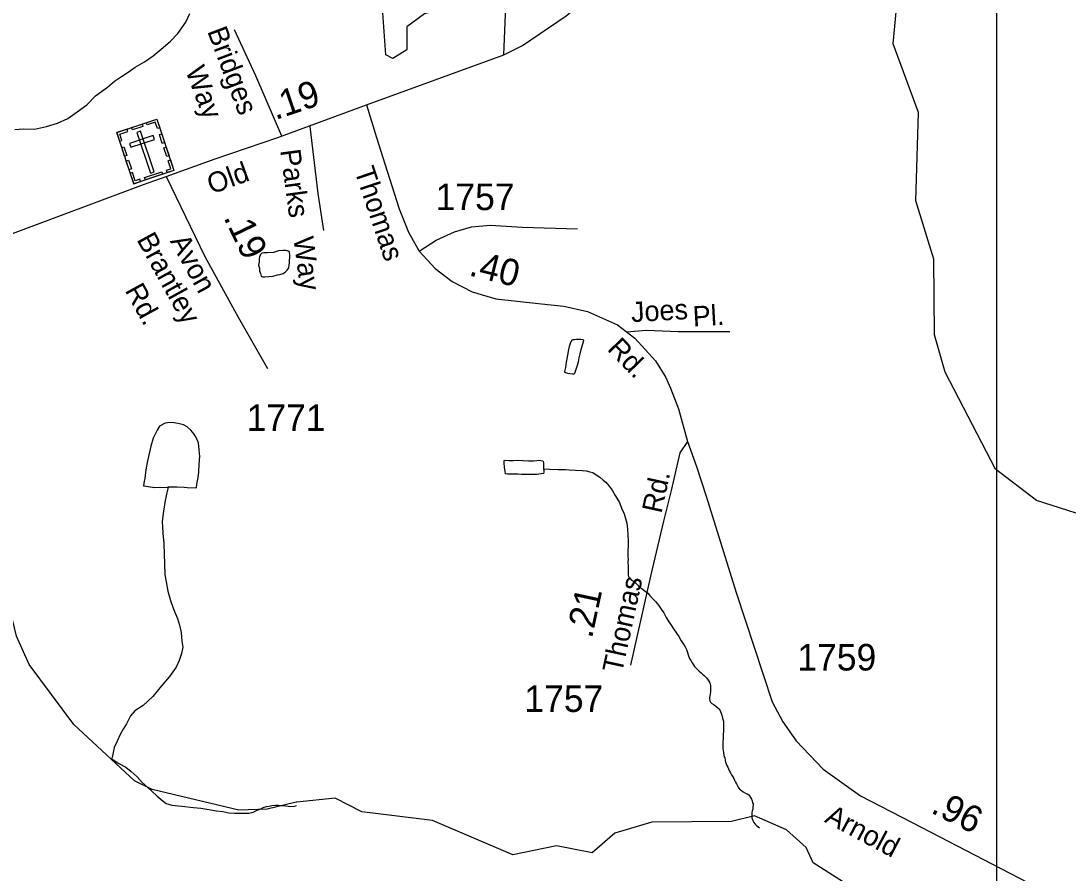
# Model space of a CAD drawing. Extents: x 2126262 to 2293712, y 749403 to 919119.
# Drawn here: x 2220963 to 2225896, y 775853 to 779867 of the extents above; entities that cross this region are included whole.
import ezdxf

# ---------------------------------------------------------------- set-up
doc = ezdxf.new("R2010")
doc.units = 0
for name, color, linetype in [('Exist Cultural Cemetery CELL', 7, 'Continuous'), ('Exist Hydrographic Creek Single Shore', 7, 'Continuous'), ('Exist Hydrographic Misc Water Feature', 7, 'Continuous'), ('Exist Hydrographic Pond Over 1500 Sq Ft', 7, 'Continuous'), ('Exist Road Non-System Type 51', 7, 'Continuous'), ('Exist Road Non-System Type 51 Label', 7, 'Continuous'), ('Exist Road Secondary Mileage Hundredths English Label', 7, 'Continuous'), ('Exist Road Secondary Type 41 Attributed', 7, 'Continuous'), ('Exist Road Secondary Type 51 Attributed', 7, 'Continuous'), ('Exist Road Secondary Type 51 Label', 7, 'Continuous'), ('Exist Road Secondary Type 51 Number Label', 7, 'Continuous'), ('Map Preparation Inset Cut Line', 7, 'Continuous')]:
    doc.layers.add(name, color=color, linetype=linetype)

msp = doc.modelspace()

# ---------------------------------------------------------------- linework, layer by layer
at = {"layer": 'Exist Cultural Cemetery CELL'}
for points in [[(2221414.4, 779341.1), (2221603.1, 779404.3), (2221684, 779162.9), (2221495.2, 779099.7)], [(2221484.6, 779364.6), (2221533.7, 779381.1), (2221537.4, 779370.3), (2221488.2, 779353.8)], [(2221617, 779363.2), (2221606.2, 779359.6), (2221596, 779390.2), (2221557.5, 779377.3), (2221554, 779387.8), (2221603.2, 779404.3)], [(2221428.1, 779300), (2221438.9, 779303.7), (2221428.6, 779334.2), (2221467.1, 779347), (2221463.6, 779357.6), (2221414.4, 779341.1)], [(2221474.7, 779289.5), (2221480.6, 779271.8), (2221592.2, 779309.2), (2221586.3, 779326.9)], [(2221527, 779348), (2221509.3, 779342), (2221573.7, 779149.7), (2221591.4, 779155.7)], [(2221629.3, 779290.3), (2221615.6, 779331.4), (2221626.4, 779335), (2221640.1, 779293.9)], [(2221451.6, 779229.7), (2221437.9, 779270.8), (2221448.7, 779274.4), (2221462.4, 779233.3)], [(2221650.2, 779227.8), (2221636.5, 779268.9), (2221647.3, 779272.5), (2221661, 779231.4)], [(2221652.6, 779152.4), (2221648.9, 779163.3), (2221669.8, 779170.2), (2221656.9, 779208.6), (2221667.5, 779212.1), (2221684, 779162.9)], [(2221473, 779166), (2221459.2, 779207.1), (2221470, 779210.7), (2221483.7, 779169.6)], [(2221526.5, 779110.2), (2221522.9, 779121.1), (2221502, 779114.1), (2221489.2, 779152.4), (2221478.6, 779148.9), (2221495.1, 779099.7)], [(2221546, 779128.8), (2221626.5, 779155.7), (2221630.1, 779144.9), (2221549.6, 779118)]]:
    msp.add_lwpolyline(points, close=True, dxfattribs=at)
at = {"layer": 'Exist Hydrographic Creek Single Shore'}
for points in [[(2227377, 776045), (2227258, 776296.7), (2227265, 776486.8), (2227240, 776503.7), (2227222, 776635.3), (2227171.9, 776685.6), (2226997, 776708.8), (2226745, 776950.2), (2226684.9, 777115.5), (2226592, 777255.1), (2226334.1, 777296.5), (2226082.1, 777501.8), (2225748, 777607.1), (2225555.1, 777755.3), (2225318, 778212.9), (2225267, 778387.8), (2225263.9, 778745.4), (2225179, 779019.4), (2225191.9, 779435.7), (2225072, 779759.7), (2225103, 780093.6)], [(2222260.2, 776186.5), (2222122.9, 776153.1), (2221989.8, 776149.3), (2221580.9, 776246.2), (2221497.9, 776287.4), (2221212.9, 776552.3), (2221001.9, 776835.5), (2220943, 776967.9), (2220780, 777633.8), (2220687.9, 777806.3), (2220326, 778263.1)], [(2224418.9, 776122.3), (2224311, 776094.9), (2223936, 776092.8), (2223761.9, 776040.7), (2223654, 775947.8), (2223486.9, 775980.7), (2223280, 775939), (2222902.9, 776100.9), (2222569.9, 776140.6), (2222444, 776205.6), (2222262.7, 776187.1)], [(2225985.9, 774387), (2225979.9, 774406.6), (2225972.7, 774423.7), (2225976.8, 774466.1), (2225985.3, 774509.9), (2225969, 774563.2), (2225976.4, 774612.2), (2225958.7, 774657.9), (2225952.1, 774702.5), (2225968.5, 774735.1), (2225943.4, 774771), (2225910.8, 774785.1), (2225890.1, 774788.4), (2225862, 774869), (2225817.9, 775207.8), (2225515.9, 775446.9), (2224929.8, 775750.9), (2224695.9, 775900.1), (2224661.8, 775972.9), (2224570, 776056.9), (2224418.9, 776122.3)]]:
    msp.add_lwpolyline(points, dxfattribs=at)
at = {"layer": 'Exist Hydrographic Misc Water Feature'}
for points in [[(2220935.1, 779356.3), (2220975.5, 779358.7), (2221027, 779357), (2221083, 779369.6), (2221135, 779385.7), (2221184.7, 779408.2), (2221228.3, 779438.5), (2221274.5, 779472.6), (2221314.2, 779514.9), (2221371.5, 779555.3), (2221403.4, 779583.7), (2221437.7, 779605.8), (2221469.1, 779626.2), (2221501.1, 779650.1), (2221544.7, 779674.4), (2221586.8, 779702.9), (2221633.9, 779741.2), (2221668.4, 779771.3), (2221702, 779807.6), (2221739.5, 779861.6), (2221759.4, 779902)], [(2222183.3, 778673.3), (2222199.3, 778677.4), (2222209.7, 778685.5), (2222216.9, 778693.4), (2222224.9, 778703.5), (2222227.3, 778717.8), (2222229, 778725.6), (2222230.6, 778765.6), (2222228.8, 778775.6), (2222226.9, 778781.5), (2222212.6, 778785.3), (2222196.8, 778785.2), (2222176.7, 778783.5), (2222152.5, 778776.9), (2222124.6, 778775), (2222106.8, 778774.9), (2222098.8, 778772.9), (2222093, 778768.5), (2222086.7, 778756.8), (2222085.2, 778744.5), (2222085.2, 778732.7), (2222083, 778716.5), (2222087.1, 778702.5), (2222087.3, 778688.6), (2222091.2, 778676.6), (2222095.7, 778664.6), (2222101.9, 778660.8), (2222111.7, 778661), (2222131.4, 778662.9), (2222151.5, 778665.1), (2222171.6, 778671), (2222183.3, 778673.3)], [(2223537.4, 778291.9), (2223531.7, 778260), (2223528, 778234.2), (2223523.9, 778215.7), (2223523.9, 778212.1), (2223538.4, 778207.9), (2223549.9, 778206.1), (2223562, 778204.3), (2223570, 778204.3), (2223572.1, 778208.4), (2223583.8, 778240.4), (2223589.7, 778260.6), (2223593.4, 778280.7), (2223597.3, 778298.8), (2223603, 778318.6), (2223609, 778340.8), (2223613.1, 778354.8), (2223614.7, 778362.6), (2223610.8, 778364.5), (2223598.7, 778366.7), (2223580.5, 778366.6), (2223570.8, 778364.4), (2223562.9, 778364.4), (2223556.9, 778362.1), (2223551.2, 778347.9), (2223546.7, 778334), (2223543, 778319.9), (2223537.4, 778291.9)], [(2221658.9, 777672.2), (2221698.9, 777672.2), (2221732.6, 777670.8), (2221746.7, 777668.6), (2221790.6, 777666.9), (2221792.4, 777684.9), (2221798.2, 777716.9), (2221802.1, 777743.1), (2221803.7, 777778.9), (2221805.6, 777815.1), (2221803.7, 777847.1), (2221799.2, 777879), (2221788.9, 777904.9), (2221778.9, 777921), (2221762.9, 777938.8), (2221746.7, 777954.6), (2221728.5, 777964.3), (2221704.3, 777970.4), (2221672.5, 777976), (2221654.2, 777973.9), (2221642.5, 777972), (2221616.7, 777957.7), (2221604.4, 777939.6), (2221587, 777901.3), (2221575.1, 777863.3), (2221557.9, 777787.2), (2221554, 777761.5), (2221550.3, 777739.3), (2221546.6, 777711.4), (2221544.5, 777699.2), (2221542.5, 777687.3), (2221540.8, 777677), (2221562.6, 777673.3), (2221592.7, 777669.6), (2221652.6, 777669.9), (2221658.9, 777672.2)], [(2223425.5, 777757.2), (2223425.9, 777749.4), (2223425.9, 777741.3), (2223425.7, 777735.2), (2223391.8, 777731), (2223371.9, 777730.8), (2223351.9, 777731), (2223322.1, 777730.6), (2223305.9, 777732.3), (2223291.8, 777732.3), (2223278.2, 777731.9), (2223266.3, 777732.1), (2223256.1, 777732.1), (2223246.3, 777733.9), (2223244, 777746), (2223241.7, 777763.8), (2223239.5, 777785.7), (2223239.5, 777793.8), (2223241.5, 777797.9), (2223263.3, 777795.9), (2223281.5, 777795.9), (2223301.4, 777798.2), (2223353.7, 777794.8), (2223377.5, 777794.8), (2223393.5, 777796.9), (2223405.4, 777797.1), (2223421.2, 777795.1), (2223423.6, 777791.1), (2223425.5, 777785.2), (2223425.7, 777773.4), (2223425.5, 777757.2)], [(2223425.5, 777757.2), (2223455.4, 777755.5), (2223493.7, 777753.7), (2223509.5, 777754.2), (2223528, 777754.3), (2223545.4, 777752.5), (2223575.8, 777750.7), (2223607.8, 777748.7), (2223625.6, 777746.8), (2223643.8, 777743.3), (2223658, 777739.1), (2223673.8, 777729.4), (2223690.2, 777717.6), (2223706.2, 777703.9), (2223718.5, 777693.9), (2223734.7, 777676), (2223748.2, 777656.1), (2223762.6, 777632), (2223782.9, 777598.2), (2223792.9, 777572.3), (2223805.4, 777544.4), (2223812, 777522.7), (2223817.5, 777500.8), (2223820.2, 777472.8), (2223822.2, 777444.5), (2223824.5, 777416.6), (2223824.7, 777394.7), (2223822.7, 777370.6), (2223822.7, 777344.7), (2223823.3, 777330.8), (2223823.1, 777316.6), (2223823.5, 777298.7), (2223823.7, 777289), (2223823.7, 777274.7), (2223823.7, 777266.6), (2223823.7, 777256.9), (2223825.9, 777248.8), (2223830, 777243), (2223839.7, 777233), (2223849.7, 777227), (2223857.9, 777219.3), (2223870.4, 777207.3), (2223882.3, 777197.3), (2223898.1, 777185.6), (2223916.2, 777171.5), (2223926.6, 777159.8), (2223938.7, 777145.8), (2223952.7, 777132), (2223967, 777114), (2223978.9, 777095.9), (2223991.2, 777078.2), (2224003.3, 777056.6), (2224015.2, 777036.5), (2224023.6, 777024.7), (2224037.8, 777002.7), (2224051.9, 776982.7), (2224061.9, 776967), (2224074.3, 776946.9), (2224084.1, 776931.2), (2224092.7, 776918.9), (2224098.4, 776905.1), (2224102.8, 776891), (2224106.6, 776881.1), (2224113, 776863.1), (2224119.2, 776853.3), (2224125.1, 776843.5), (2224131.1, 776833.6), (2224137, 776825.4), (2224143.1, 776819.6), (2224151.1, 776811.5), (2224157.1, 776805.8), (2224167.3, 776795.7), (2224173.5, 776789.9), (2224181.5, 776783.8), (2224187.2, 776778.1), (2224193.6, 776771.8), (2224201.6, 776762.1), (2224207.7, 776752.3), (2224209.8, 776744.3), (2224211.8, 776734.2), (2224211.8, 776724.1), (2224212, 776714.3), (2224212.3, 776706.2), (2224210.2, 776696.3), (2224207.9, 776688.1), (2224206.7, 776680.2), (2224206.5, 776674.1), (2224208.4, 776664.1), (2224212.5, 776658.2), (2224218.2, 776652.1), (2224228.9, 776644.5), (2224236.7, 776638.4), (2224246.9, 776630.4), (2224250.4, 776626.6), (2224256.7, 776618.7), (2224260.6, 776608.8), (2224265.2, 776596.8), (2224269.1, 776582.8), (2224273.2, 776568.8), (2224273.4, 776554.5)], [(2221658.9, 777672.2), (2221654.6, 777663.9), (2221646.8, 777630.2), (2221643.2, 777608), (2221635.4, 777558.1), (2221631.7, 777535.9), (2221629.4, 777507.9), (2221630, 777485.9), (2221632.1, 777451.9), (2221636.4, 777406.2), (2221638.8, 777351.9), (2221639.5, 777312.1), (2221641.5, 777258.2), (2221647.7, 777224), (2221655.7, 777180.2), (2221668.4, 777136.5), (2221680.7, 777100.5), (2221686.4, 777084.6), (2221701.2, 777052.5), (2221711, 777020.5), (2221717.4, 776986.7), (2221721.9, 776944.7), (2221725.8, 776916.9), (2221719.8, 776886.9), (2221708.2, 776854.6), (2221694.4, 776822.6), (2221662.6, 776778.3), (2221617.1, 776726), (2221585.3, 776684.1), (2221539.6, 776641.5), (2221500, 776617.5), (2221480.1, 776593.3), (2221460.2, 776555.4), (2221444.9, 776530.9), (2221430.7, 776505), (2221417.2, 776474.6), (2221403.2, 776444.7), (2221393.6, 776396.6), (2221389.5, 776390.8)], [(2224273.4, 776554.5), (2224273.4, 776538.8), (2224273.6, 776522.9), (2224271.9, 776504.9), (2224271.7, 776486.6), (2224269.7, 776468.7), (2224270.1, 776450.8), (2224270.3, 776439), (2224272.3, 776420.8), (2224274.2, 776406.7), (2224278.7, 776394.8), (2224280.9, 776383), (2224283, 776375), (2224285, 776367), (2224288.7, 776359.1), (2224293, 776350.8), (2224296.7, 776343.3), (2224301, 776332.9), (2224305.3, 776325), (2224311.3, 776315.1), (2224317.2, 776305.3), (2224321.5, 776297.4), (2224325.2, 776289.5), (2224329.3, 776281.2), (2224333.6, 776273.3), (2224339.6, 776263.4), (2224343.5, 776253.5), (2224351.9, 776245.3), (2224357.6, 776241.6), (2224366, 776235.5), (2224376.1, 776229.5), (2224383.9, 776225.9), (2224391.7, 776221.8), (2224396, 776215.9), (2224400.1, 776208.1), (2224404.4, 776200.1), (2224408.5, 776192.2), (2224410.1, 776184.2), (2224412.6, 776178.2), (2224412.4, 776172.1), (2224410.7, 776164.3), (2224410.7, 776154.1), (2224408.5, 776145.9), (2224406.8, 776136), (2224406.8, 776125.9), (2224406.6, 776112.1), (2224410.9, 776100.1), (2224415.3, 776090.1), (2224421.2, 776084.4), (2224429.2, 776076.3), (2224443.3, 776066.4)], [(2221389.5, 776390.8), (2221393.4, 776388.5), (2221423.7, 776369), (2221457.8, 776351.3), (2221482.2, 776331.3), (2221510.1, 776305.7), (2221534.3, 776279.7), (2221560.5, 776255.8), (2221580.4, 776238.2), (2221604.6, 776214.3), (2221632.9, 776190.6), (2221647, 776180.7), (2221659.1, 776176.8), (2221674.9, 776172.8), (2221720.9, 776167.1), (2221776.8, 776161.5), (2221810.9, 776157.6), (2221884.7, 776146.4), (2221914.6, 776142.3), (2221943.1, 776136.8), (2221969.2, 776134.9), (2221999.3, 776135.2), (2222021.1, 776135.2), (2222037.1, 776135.2), (2222056.9, 776139.5), (2222076.8, 776149.5), (2222092.8, 776155.6), (2222104.9, 776161.9), (2222120.9, 776166), (2222132.8, 776168.2), (2222144.5, 776170.5), (2222162.8, 776172.6), (2222176.9, 776172.9), (2222191.1, 776171.2), (2222209.1, 776169.7), (2222235.1, 776166.1), (2222253, 776168.3), (2222261, 776170.4)], [(2222262.7, 776187.1), (2222260.2, 776186.5)]]:
    msp.add_lwpolyline(points, dxfattribs=at)
at = {"layer": 'Exist Hydrographic Pond Over 1500 Sq Ft'}
msp.add_lwpolyline([(2222701, 780480.9), (2222909.1, 780525.8), (2223044, 780300), (2223128.9, 780058.8), (2223096.9, 779961), (2222864, 779900.3), (2222780.9, 779839.6), (2222782, 779731.3), (2222715.9, 779690), (2222681.9, 779707.1), (2222663, 779973.3), (2222561.9, 780155.8), (2222527.1, 780379.5), (2222701, 780480.9)], dxfattribs=at)
at = {"layer": 'Exist Road Non-System Type 51'}
for points in [[(2223238.7, 779707.8), (2223247.3, 779936.3), (2223241.7, 780313.5), (2223245.9, 780817.7), (2223237.5, 780893.2), (2223215.2, 780977), (2223173.3, 781044), (2223128.7, 781080.4), (2223131.5, 781348.6), (2223139.8, 781648.3), (2223111.8, 781690.2), (2223058.8, 781729.3), (2222930.4, 781771.2)], [(2222191.8, 779324.2), (2222069.9, 779608), (2221968.8, 779825.7)], [(2222324.2, 779369.7), (2222362.2, 779053.8), (2222388.6, 778880.1)], [(2222838.9, 778782.3), (2222919.7, 778834.4), (2223005.6, 778873.8), (2223085.2, 778896.5), (2223173.2, 778904.8), (2223324.2, 778895.5), (2223585, 778887.2)], [(2223817.3, 778401.9), (2223909.4, 778410.2), (2224058.9, 778403.6), (2224302.8, 778403.6)]]:
    msp.add_lwpolyline(points, dxfattribs=at)
at = {"layer": 'Exist Road Secondary Type 41 Attributed'}
for points in [[(2221647.4, 779134), (2221829.7, 778756.7), (2221986, 778471.7), (2222124.6, 778230.3)], [(2224102.9, 777886.3), (2224067.7, 777832.1), (2224026.5, 777655.7), (2223990.8, 777510), (2223929.3, 777250.6), (2223835.4, 776831.3)]]:
    msp.add_lwpolyline(points, dxfattribs=at)
at = {"layer": 'Exist Road Secondary Type 51 Attributed'}
for points in [[(2222591.7, 779471.1), (2223238.7, 779707.8), (2223326.7, 779751.1), (2223532.5, 779891.4), (2223607.9, 779955.7), (2223831.9, 780130.3), (2224247.2, 780476.1), (2224970.8, 781060.7), (2225247.9, 781307.2), (2225811, 781830.3), (2226026, 782003.6), (2226551.4, 782410.7), (2226709.1, 782550.4), (2226842.4, 782686.6), (2226982.2, 782846.8)], [(2221647.4, 779134), (2221877.8, 779217.7), (2222173.8, 779318), (2222591.7, 779471.1)], [(2222591.7, 779471.1), (2222638.4, 779318.1), (2222689.2, 779159.4), (2222744.7, 778981.3), (2222789, 778871.8), (2222838.9, 778782.3), (2222915.4, 778701), (2222994.3, 778638.9), (2223089.3, 778590.6), (2223201.3, 778558.4), (2223415.4, 778535), (2223520.9, 778523.7), (2223632, 778498.8), (2223773, 778435.9), (2223855.9, 778372.3), (2223952.5, 778265.9), (2224001.6, 778187.8), (2224022.6, 778137.8), (2224060.7, 778040.3), (2224102.9, 777886.3)], [(2218183.6, 777909.8), (2218417.6, 777977), (2219440.7, 778338.4), (2220305.8, 778648.2), (2220729.3, 778794.2), (2221540, 779096.8), (2221647.4, 779134)], [(2224102.9, 777886.3), (2224146.3, 777767.6), (2224191.5, 777628.7), (2224332.9, 777174.2), (2224502.5, 776659.4), (2224552.7, 776565.8), (2224615.5, 776475), (2224743.2, 776341.6), (2224919.1, 776215.9), (2225208, 776066.5), (2226078.2, 775614.6), (2226420.9, 775435.1), (2226518.6, 775352.6), (2226621.9, 775240.9), (2226672.1, 775134.7), (2226739.8, 774970.6), (2226756.5, 774857.4), (2226756.5, 774728.9), (2226753, 774534.4), (2226714.9, 774408.9), (2226672, 774316.8), (2226543.4, 774130.3)]]:
    msp.add_lwpolyline(points, dxfattribs=at)
at = {"layer": 'Map Preparation Inset Cut Line'}
msp.add_lwpolyline([(2225559.9, 781102.8), (2225559.9, 762528.3), (2216266.9, 762528.3), (2206391.5, 779996.5), (2206391.5, 781102.8)], close=True, dxfattribs=at)

# ---------------------------------------------------------------- texts
at = {"layer": 'Exist Road Non-System Type 51 Label'}
for s, rotation, p in [('Bridges', 290.7501, (2221839.8, 779818.9)), ('Way', 290.7501, (2221736.6, 779633.9)), ('Parks', 277.7125, (2222184.6, 779257.5)), ('Way', 277.7125, (2222246.5, 778844.5)), ('Joes', 3.1822, (2223839.8, 778447.7)), ('Pl.', 3.1822, (2224130.8, 778427.7))]:
    msp.add_text(s, height=95, rotation=rotation, dxfattribs=at).set_placement(p)
at = {"layer": 'Exist Road Secondary Mileage Hundredths English Label'}
for s, rotation, p in [('.19', 18.7164, (2222161.7, 779399.7)), ('.19', 295.7962, (2221916.1, 778941.6)), ('.40', 345.9521, (2223069, 778669.1)), ('.21', 77.9175, (2223653.2, 776954.3)), ('.96', 333.3243, (2225244.6, 776139.5))]:
    msp.add_text(s, height=125, rotation=rotation, dxfattribs=at).set_placement(p)
at = {"layer": 'Exist Road Secondary Type 51 Label'}
for s, rotation, p in [('Old', 20.0121, (2221861.2, 779049.5)), ('Thomas', 288.553, (2222533.3, 779162.6)), ('Brantley', 298.8057, (2221506.5, 778837.5)), ('Avon', 298.8057, (2221664.2, 778829.9)), ('Rd.', 298.8057, (2221451.1, 778597.9)), ('Rd.', 314.0258, (2223721.3, 778318.6)), ('Rd.', 77.7023, (2223980.6, 777543.6)), ('Thomas', 77.7023, (2223794.4, 776790.5)), ('Arnold', 332.0587, (2224744.9, 776095.2))]:
    msp.add_text(s, height=95, rotation=rotation, dxfattribs=at).set_placement(p)
at = {"layer": 'Exist Road Secondary Type 51 Number Label'}
for s, p in [('1757', (2222916.8, 778975.9)), ('1771', (2222026.3, 777935.1)), ('1759', (2224620.9, 776806.9)), ('1757', (2223334.8, 776611.6))]:
    msp.add_text(s, height=125, dxfattribs=at).set_placement(p)

doc.saveas('drawing.dxf')
